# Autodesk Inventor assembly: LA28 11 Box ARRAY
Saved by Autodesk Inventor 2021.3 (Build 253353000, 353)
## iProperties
Created: 2023-01
Part Number: LA28 11 Box ARRAY
Document SubType Name: Assembly
Designer: AdminForWorker
Title: LA28 11 Box ARRAY v5
Author: AdminForWorker
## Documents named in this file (3)
- c:\worker\convert-fusion-r08-cosv3\tmp\job-1\5\output\files\a86acfbb-7093-441b-87ec-5aa5153615de\25883e21-57c3-4f00-9a9e-e6c77d234e43.iam
- c:\worker\convert-fusion-r08-cosv3\tmp\job-1\5\output\files\a86acfbb-7093-441b-87ec-5aa5153615de\LA28 RF1 Sheet Metal Assembly v3.iam
- c:\worker\convert-fusion-r08-cosv3\tmp\job-1\5\output\files\a86acfbb-7093-441b-87ec-5aa5153615de\LA28 TOUR BLOCK v2.ipt
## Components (12 placed, 2 different names)
1. LA28 RF1 Sheet Metal Assembly v3:1 [sub-assembly]
2. LA28 TOUR BLOCK v2:1
3. LA28 TOUR BLOCK v2:2
4. LA28 TOUR BLOCK v2:3
5. LA28 TOUR BLOCK v2:4
6. LA28 TOUR BLOCK v2:5
7. LA28 TOUR BLOCK v2:6
8. LA28 TOUR BLOCK v2:7
9. LA28 TOUR BLOCK v2:8
10. LA28 TOUR BLOCK v2:9
11. LA28 TOUR BLOCK v2:10
12. LA28 TOUR BLOCK v2:11
